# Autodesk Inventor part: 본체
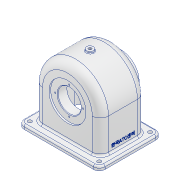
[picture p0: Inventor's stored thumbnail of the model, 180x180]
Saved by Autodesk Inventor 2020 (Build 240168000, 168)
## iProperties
Created: 2022-09
Part Number: 본체
Material: 알루미늄 6061
Document SubType Name: Modeling
Designer: Administrator
Density: 2.7 g/cm^3
Appearance: 알루미늄 - 평지
Mass: 785.263 g
Surface Area: 1042.64 cm^2
Volume: 290.838 cm^3
Author: Administrator
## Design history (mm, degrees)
sketch "스케치1"
  geometry: L1 (70, -54)-(-70, -54); L2 (-70, -54)-(-70, 54); L3 (-70, 54)-(70, 54); L4 (70, 54)-(70, -54); L5 (70, -54)-(-70, 54); L6 (-70, -54)-(70, 54); 1 further point
  constraints: 12 end point, 2 midpoint, 2 parallel, 1 horizontal, 1 perpendicular
  dimensions: "d0" = 140 distance of L1.start L1.end; "d1" = 108 distance of L3.end L1.start
extrude "돌출1" new body sketch "스케치1" distance "d2" = 7; taper "d3" = 0 deg
sketch "스케치3" dims "d5" = 114
  geometry: L1 (70, 0)-(-70, 0) reference; L2 (-70, 0)-(-70, 7) reference; L3 (70, 7)-(-70, 7) reference; L4 (70, 0)-(70, 7) reference; L5 (70, 7)-(-70, 7) reference; L6 (-57, 7)-(57, 7); L7 (57, 7)-(57, 64); L8 (57, 64)-(-57, 64); L9 (-57, 64)-(-57, 7); 3 further points
  constraints: 8 end point, 2 parallel, 1 horizontal, 1 midpoint, 1 perpendicular, 1 point on line, 1 vertical alignment, 3 other
  dimensions: "d4" = 64 distance between parallel lines of L1 L8
extrude "돌출2" join sketch "스케치3" stored distance "d6" = 78; taper "d7" = 0 deg
sketch "스케치4"
  geometry: L1 (-70, 0)-(70, 0) reference; C1 r 32 at (0, 64); A1 r 57 centre (0, 64) between (57, 64) and (-57, 64) reference; 2 further points
  constraints: 1 centre point, 1 coincident, 1 midpoint, 1 vertical alignment
  dimensions: "d8" = 64 diameter of C1
extrude "돌출3" cut sketch "스케치4" distance "d9" = 3; taper "d10" = 0 deg
sketch "스케치5"
  geometry: L1 (64, 39)-(7, 39) reference; L2 (64, -39)-(64, 39) reference; L3 (64, 20)-(64, -34); L4 (64, 20)-(92, 20); L5 (92, 20)-(100.083, 34); L6 (100.083, 34)-(116, 34); L7 (116, 34)-(116, -34); L8 (116, -34)-(64, -34); L9 (0, -54)-(7, -54) reference; L10 (32, 39)-(96, 39) reference; L11 (121, -39)-(121, 39) reference; L12 (0, -54)-(0, 54) reference; 3 further points
  constraints: 12 end point, 2 perpendicular, 1 collinear, 1 horizontal, 1 parallel
  dimensions: "d11" = 20 distance between parallel lines of L9 L8; "d12" = 5 distance between parallel lines of L10 L6; "d13" = 60 deg angle of L4 L5; "d14" = 56 diameter of L4.end L2; "d15" = 14 distance between parallel lines of L4 L6; "d16" = 5 distance between parallel lines of L11 L7; "d17" = 64 distance between parallel lines of L12 L3
revolve "회전1" sketch "스케치5" stored, may be unused: angle "d18" = 90 deg
sketch "스케치7"
  geometry: L1 (52, 34)-(-52, 34); L2 (-52, 34)-(-52, -34); L3 (-52, -34)-(52, -34); L4 (52, -34)-(52, 34); L5 (52, 34)-(-52, -34); L6 (-52, 34)-(52, -34); 1 further point
  constraints: 12 end point, 2 midpoint, 2 parallel, 1 horizontal, 1 perpendicular
  dimensions: "d20" = 104 distance of L2.end L3.end; "d21" = 68 distance of L3.end L1.start
extrude "돌출4" cut sketch "스케치7" stored distance "d22" = 5; taper "d23" = 0 deg
sketch "스케치8"
  geometry: L1 (64, 39)-(7, 39) reference; L2 (92, 20)-(36, 20) reference; L3 (100.083, 34)-(27.917, 34) reference; L4 (92, 20)-(36, 20) reference; L5 (84, 20)-(64, 20); L6 (64, 20)-(64, 36); L7 (64, -39)-(64, 39) reference; L8 (64, 36)-(84, 36); L9 (84, 36)-(84, 20); 6 further points
  constraints: 8 end point, 2 midpoint, 2 point on line, 1 horizontal, 1 perpendicular
  dimensions: "d24" = 16 distance of L8.end L5.start; "d26" = 40 diameter of L9 L6; "d27" = 20 distance of L5.start L5.end
revolve "회전2" sketch "스케치8" stored, may be unused: angle "d28" = 90 deg
sketch "스케치9"
  geometry: C1 r 31 at (0, 64); A1 r 57 centre (0, 64) between (57, 64) and (-57, 64) reference; 1 further point
  constraints: 1 centre point, 1 coincident
  dimensions: "d29" = 62 diameter of C1
extrude "돌출5" join sketch "스케치9" distance "d30" = 15; taper "d31" = 0 deg
sketch "스케치10"
  geometry: C1 r 31 at (0, 0) reference; C2 r 20 at (0, 0); 1 further point
  constraints: 1 centre point, 1 coincident
  dimensions: "d32" = 40 diameter of C2
extrude "돌출6" cut sketch "스케치10" distance "d33" = 16; taper "d34" = 0 deg
sketch "스케치11"
  geometry: C1 r 20 at (0, 0) reference; C2 r 17.5 at (0, 0); 1 further point
  constraints: 1 centre point, 1 coincident
  dimensions: "d35" = 35 diameter of C2
extrude "돌출7" cut sketch "스케치11" distance "d36" = 5; taper "d37" = 0 deg
node "작업 평면1"
sketch "스케치12"
  geometry: C1 r 6 at (0, 0); 1 further point
  constraints: 1 centre point, 1 coincident
  dimensions: "d39" = 12 diameter of C1
extrude "돌출8" join sketch "스케치12" stored distance "d40" = 5; taper "d41" = 0 deg
sketch "스케치13"
  geometry: C1 r 6 at (0, 0) reference; 2 further points
  constraints: 1 coincident
hole "구멍1" sketch "스케치13" at (0, 0) diameter "d42" = 5.1881; stored, may be unused: countersink angle "d46" = 90 deg, drill point angle "d48" = 118 deg; dims "d43" = 12, "d44" = 4, "d45" = 2, "d47" = 16
sketch "스케치14" dims "d49" = 48
  geometry: L1 (57, -57)-(57, 0) reference; C1 r 32 at (0, 0) reference; 3 further points
  constraints: 1 coincident, 1 vertical alignment, 2 other
  dimensions: "d50" = 57 distance from line of L1 point (0, 24)
hole "구멍2" sketch "스케치14" at (0, 24) diameter "d51" = 2.459; stored, may be unused: countersink angle "d55" = 90 deg, drill point angle "d57" = 118 deg; dims "d52" = 7, "d53" = 4, "d54" = 2, "d56" = 9
sketch "스케치15"
  geometry: C1 r 17.5 at (0, 0) reference; C2 r 24 at (0, 0); C3 r 1.23 at (0, 24) reference; 2 further points
  constraints: 2 coincident, 1 centre point
  dimensions: "d61" = 24 radius of C2
hole "구멍3" sketch "스케치15" at (0, 24) diameter "d62" = 2.459; stored, may be unused: countersink angle "d66" = 90 deg, drill point angle "d68" = 118 deg; dims "d63" = 7, "d64" = 4, "d65" = 2, "d67" = 9
sketch "스케치16"
  geometry: L1 (0, 57)-(78, 57) reference; L2 (0, 0)-(0, 57) reference; L3 (-15, -7)-(93, -7) reference; 3 further points
  constraints: 1 midpoint, 1 vertical alignment, 1 other
  dimensions: "d72" = 17 distance from line of L3 point (39, 10); "d92" = 39 distance from line of L2 point (39, 10) (derived)
feature "엠보싱1" sketch "스케치16" dims "d0" = 140, "d1" = 108, "d73" = 0.5, "d74" = 0
fillet "모깎기1" dims "d75" = 9
fillet "모깎기2" dims "d76" = 0.6
chamfer "모따기1" distance "d77" = 1; stored, may be unused: second distance "d78" = 2, angle "d79" = 45 deg
fillet "모깎기3" dims "d80" = 14
fillet "모깎기4" dims "d81" = 10
sketch "스케치17"
  geometry: A1 r 10 centre (-60, 44) between (-60, 54) and (-70, 44) reference; A2 r 10 centre (-60, -44) between (-70, -44) and (-60, -54) reference; A3 r 10 centre (60, -44) between (60, -54) and (70, -44) reference; A4 r 10 centre (60, 44) between (70, 44) and (60, 54) reference; 1 further point
hole "구멍4" sketch "스케치17" at (-60, -44), (-60, 44), (60, 44), (60, -44) diameter "d82" = 6.6; stored, may be unused: countersink angle "d86" = 90 deg, drill point angle "d88" = 118 deg; dims "d83" = 7, "d84" = 4, "d85" = 2, "d87" = 9
fillet "모깎기5" dims "d89" = 3
fillet "모깎기6" dims "d90" = 1
fillet "모깎기7" dims "d91" = 3
node "솔리드1"
pattern_circular "원형 패턴1" dims angle "d59" = 360 deg
pattern_circular "원형 패턴2" dims angle "d70" = 360 deg
node "투영된 루프1"
node "투영된 루프2"
feature "A9D066F2-1C7D-4E18-AEED-F7BC21143FA4" dims "d82" = 6.6, "d83" = 7, "d84" = 4, "d85" = 2, "d86" = 90 deg, "d87" = 9, "d88" = 118 deg
other parameters: "d38" = 124
